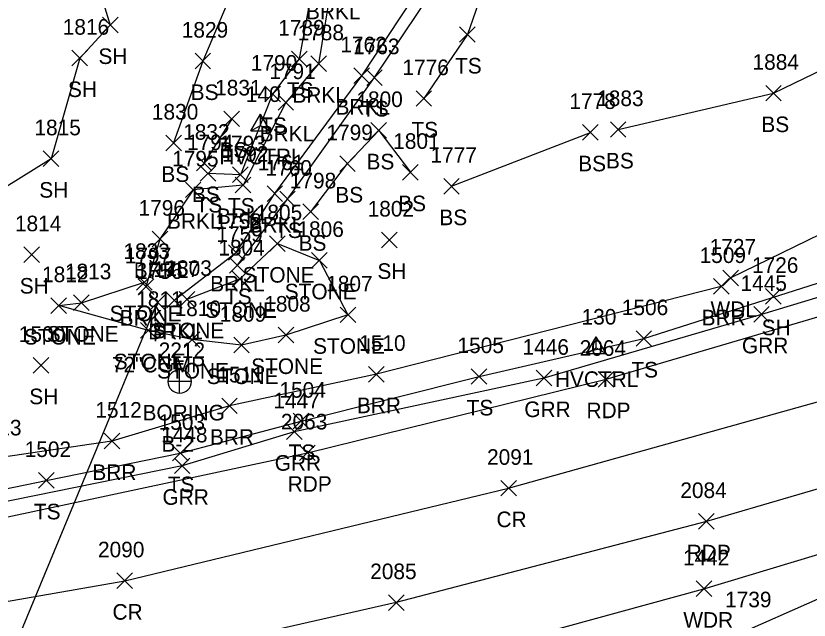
# Model space of a CAD drawing. Extents: x 1526508 to 1531550, y 369926 to 373082.
# Drawn here: x 1531067.4 to 1531169.1, y 370143.1 to 370220.6 of the extents above; entities that cross this region are included whole.
import ezdxf

# ---------------------------------------------------------------- set-up
doc = ezdxf.new("R2010")
doc.units = 0
for name, color, linetype in [('C_A', 7, 'Continuous'), ('C_I', 7, 'Continuous'), ('CPSM', 7, 'Continuous'), ('D_A', 7, 'Continuous'), ('D_C', 7, 'Continuous'), ('D_I', 7, 'Continuous'), ('D_TIC', 7, 'Continuous'), ('DCP', 7, 'Continuous'), ('G_A', 7, 'Continuous'), ('G_C', 7, 'Continuous'), ('G_I', 7, 'Continuous'), ('GA_P', 7, 'Continuous'), ('L_A', 7, 'Continuous'), ('L_I', 7, 'Continuous'), ('L_TIC', 7, 'Continuous'), ('LABL', 7, 'Continuous'), ('LASF', 7, 'Continuous'), ('LAWA', 7, 'Continuous'), ('LAWE', 7, 'Continuous'), ('LELB', 7, 'Continuous'), ('LSOGP', 7, 'Continuous'), ('P_A', 7, 'Continuous'), ('P_I', 7, 'Continuous'), ('P_TIC', 7, 'Continuous'), ('PET', 7, 'Continuous'), ('PRC', 7, 'Continuous'), ('R_A', 7, 'Continuous'), ('R_I', 7, 'Continuous'), ('R_TIC', 7, 'Continuous'), ('RGR', 7, 'Continuous')]:
    doc.layers.add(name, color=color, linetype=linetype)

msp = doc.modelspace()

# ---------------------------------------------------------------- linework, layer by layer
at = {"layer": 'CPSM'}
for p, q in [((1531097.55, 370205.87), (1531098.8, 370208.03)), ((1531100.05, 370205.87), (1531098.8, 370208.03)), ((1531098.8, 370206.59), (1531098.8, 370208.03)), ((1531097.55, 370205.87), (1531098.8, 370206.59)), ((1531097.55, 370205.87), (1531100.05, 370205.87)), ((1531098.8, 370206.59), (1531098.8, 370206.59)), ((1531098.8, 370206.59), (1531100.05, 370205.87)), ((1531140.6, 370177.3), (1531141.85, 370179.47)), ((1531143.1, 370177.3), (1531141.85, 370179.47)), ((1531141.85, 370178.03), (1531141.85, 370179.47)), ((1531140.6, 370177.3), (1531141.85, 370178.03)), ((1531140.6, 370177.3), (1531143.1, 370177.3)), ((1531141.85, 370178.03), (1531141.85, 370178.03)), ((1531141.85, 370178.03), (1531143.1, 370177.3))]:
    msp.add_line(p, q, dxfattribs=at)
at = {"layer": 'D_TIC'}
for points in [[(1531084.61, 370182.89), (1531086.61, 370184.89)], [(1531086.61, 370182.89), (1531084.61, 370184.89)]]:
    msp.add_lwpolyline(points, dxfattribs=at)
at = {"layer": 'DCP'}
msp.add_lwpolyline([(1531055.49, 370099.7), (1531060.38, 370123.1), (1531085.61, 370183.89)], dxfattribs=at)
at = {"layer": 'GA_P'}
for p, q in [((1531088.43, 370173.73), (1531088.43, 370175.23)), ((1531088.43, 370173.73), (1531086.93, 370173.73)), ((1531089.93, 370173.73), (1531088.43, 370173.73)), ((1531088.43, 370172.23), (1531088.43, 370173.73))]:
    msp.add_line(p, q, dxfattribs=at)
for start, end in [(90, 180), (0, 90), (180, 270), (270, 0)]:
    msp.add_arc((1531088.43, 370173.73), 1.5, start, end, dxfattribs=at)
at = {"layer": 'L_TIC'}
for points in [[(1531078.53, 370218.46), (1531080.53, 370220.46)], [(1531080.53, 370218.46), (1531078.53, 370220.46)], [(1531124.33, 370217.24), (1531126.33, 370219.24)], [(1531126.33, 370217.24), (1531124.33, 370219.24)], [(1531074.62, 370214.22), (1531076.62, 370216.22)], [(1531076.62, 370214.22), (1531074.62, 370216.22)], [(1531102.77, 370214.11), (1531104.77, 370216.11)], [(1531104.77, 370214.11), (1531102.77, 370216.11)], [(1531090.4, 370213.84), (1531092.4, 370215.84)], [(1531092.4, 370213.84), (1531090.4, 370215.84)], [(1531105.25, 370213.5), (1531107.25, 370215.5)], [(1531107.25, 370213.5), (1531105.25, 370215.5)], [(1531110.77, 370211.96), (1531112.77, 370213.96)], [(1531112.77, 370211.96), (1531110.77, 370213.96)], [(1531112.41, 370211.72), (1531114.41, 370213.72)], [(1531114.41, 370211.72), (1531112.41, 370213.72)], [(1531099.34, 370209.6), (1531101.34, 370211.6)], [(1531101.34, 370209.6), (1531099.34, 370211.6)], [(1531118.74, 370209.03), (1531120.74, 370211.03)], [(1531120.74, 370209.03), (1531118.74, 370211.03)], [(1531163.57, 370209.72), (1531165.57, 370211.72)], [(1531165.57, 370209.72), (1531163.57, 370211.72)], [(1531101.04, 370208.52), (1531103.04, 370210.52)], [(1531103.04, 370208.52), (1531101.04, 370210.52)], [(1531094.11, 370206.42), (1531096.11, 370208.42)], [(1531096.11, 370206.42), (1531094.11, 370208.42)], [(1531112.95, 370204.94), (1531114.95, 370206.94)], [(1531114.95, 370204.94), (1531112.95, 370206.94)], [(1531143.65, 370205.06), (1531145.65, 370207.06)], [(1531145.65, 370205.06), (1531143.65, 370207.06)], [(1531140.09, 370204.69), (1531142.09, 370206.69)], [(1531142.09, 370204.69), (1531140.09, 370206.69)], [(1531086.65, 370203.33), (1531088.65, 370205.33)], [(1531088.65, 370203.33), (1531086.65, 370205.33)], [(1531070.94, 370201.31), (1531072.94, 370203.31)], [(1531072.94, 370201.31), (1531070.94, 370203.31)], [(1531090.57, 370200.74), (1531092.57, 370202.74)], [(1531092.57, 370200.74), (1531090.57, 370202.74)], [(1531108.95, 370200.68), (1531110.95, 370202.68)], [(1531110.95, 370200.68), (1531108.95, 370202.68)], [(1531091.06, 370199.41), (1531093.06, 370201.41)], [(1531093.06, 370199.41), (1531091.06, 370201.41)], [(1531095.22, 370199.26), (1531097.22, 370201.26)], [(1531097.22, 370199.26), (1531095.22, 370201.26)], [(1531117.01, 370199.57), (1531119.01, 370201.57)], [(1531119.01, 370199.57), (1531117.01, 370201.57)], [(1531095.56, 370197.93), (1531097.56, 370199.93)], [(1531097.56, 370197.93), (1531095.56, 370199.93)], [(1531122.28, 370197.78), (1531124.28, 370199.78)], [(1531124.28, 370197.78), (1531122.28, 370199.78)], [(1531089.16, 370197.32), (1531091.16, 370199.32)], [(1531091.16, 370197.32), (1531089.16, 370199.32)], [(1531099.63, 370196.83), (1531101.63, 370198.83)], [(1531101.63, 370196.83), (1531099.63, 370198.83)], [(1531101.26, 370196.13), (1531103.26, 370198.13)], [(1531103.26, 370196.13), (1531101.26, 370198.13)], [(1531104.24, 370194.5), (1531106.24, 370196.5)], [(1531106.24, 370194.5), (1531104.24, 370196.5)], [(1531084.9, 370191), (1531086.9, 370193)], [(1531086.9, 370191), (1531084.9, 370193)], [(1531114.3, 370190.89), (1531116.3, 370192.89)], [(1531116.3, 370190.89), (1531114.3, 370192.89)], [(1531099.96, 370190.41), (1531101.96, 370192.41)], [(1531101.96, 370190.41), (1531099.96, 370192.41)], [(1531068.44, 370189), (1531070.44, 370191)], [(1531070.44, 370189), (1531068.44, 370191)], [(1531094.69, 370189.28), (1531096.69, 370191.28)], [(1531096.69, 370189.28), (1531094.69, 370191.28)], [(1531094.84, 370187.64), (1531096.84, 370189.64)], [(1531096.84, 370187.64), (1531094.84, 370189.64)], [(1531105.35, 370188.27), (1531107.35, 370190.27)], [(1531107.35, 370188.27), (1531105.35, 370190.27)], [(1531082.91, 370185.45), (1531084.91, 370187.45)], [(1531084.91, 370185.45), (1531082.91, 370187.45)], [(1531095.16, 370185.89), (1531097.16, 370187.89)], [(1531097.16, 370185.89), (1531095.16, 370187.89)], [(1531158.07, 370186.01), (1531160.07, 370188.01)], [(1531160.07, 370186.01), (1531158.07, 370188.01)], [(1531083.1, 370184.89), (1531085.1, 370186.89)], [(1531085.1, 370184.89), (1531083.1, 370186.89)], [(1531156.87, 370184.93), (1531158.87, 370186.93)], [(1531158.87, 370184.93), (1531156.87, 370186.93)], [(1531163.56, 370183.66), (1531165.56, 370185.66)], [(1531165.56, 370183.66), (1531163.56, 370185.66)], [(1531071.92, 370182.47), (1531073.92, 370184.47)], [(1531073.92, 370182.47), (1531071.92, 370184.47)], [(1531074.84, 370182.84), (1531076.84, 370184.84)], [(1531076.84, 370182.84), (1531074.84, 370184.84)], [(1531086.74, 370183.15), (1531088.74, 370185.15)], [(1531088.74, 370183.15), (1531086.74, 370185.15)], [(1531088.38, 370183.27), (1531090.38, 370185.27)], [(1531090.38, 370183.27), (1531088.38, 370185.27)], [(1531109, 370181.28), (1531111, 370183.28)], [(1531111, 370181.28), (1531109, 370183.28)], [(1531083.42, 370179.29), (1531085.42, 370181.29)], [(1531085.42, 370179.29), (1531083.42, 370181.29)], [(1531101.05, 370178.69), (1531103.05, 370180.69)], [(1531103.05, 370178.69), (1531101.05, 370180.69)], [(1531089, 370178.11), (1531091, 370180.11)], [(1531091, 370178.11), (1531089, 370180.11)], [(1531095.36, 370177.4), (1531097.36, 370179.4)], [(1531097.36, 370177.4), (1531095.36, 370179.4)], [(1531146.94, 370178.24), (1531148.94, 370180.24)], [(1531148.94, 370178.24), (1531146.94, 370180.24)], [(1531069.67, 370174.81), (1531071.67, 370176.81)], [(1531071.67, 370174.81), (1531069.67, 370176.81)], [(1531112.66, 370173.66), (1531114.66, 370175.66)], [(1531114.66, 370173.66), (1531112.66, 370175.66)], [(1531125.82, 370173.37), (1531127.82, 370175.37)], [(1531127.82, 370173.37), (1531125.82, 370175.37)], [(1531093.82, 370169.61), (1531095.82, 370171.61)], [(1531095.82, 370169.61), (1531093.82, 370171.61)], [(1531102.99, 370167.65), (1531104.99, 370169.65)], [(1531104.99, 370167.65), (1531102.99, 370169.65)], [(1531078.75, 370165.09), (1531080.75, 370167.09)], [(1531080.75, 370165.09), (1531078.75, 370167.09)], [(1531087.5, 370163.53), (1531089.5, 370165.53)], [(1531089.5, 370163.53), (1531087.5, 370165.53)], [(1531070.33, 370160.04), (1531072.33, 370162.04)], [(1531072.33, 370160.04), (1531070.33, 370162.04)], [(1531154.65, 370146.14), (1531156.65, 370148.14)], [(1531156.65, 370146.14), (1531154.65, 370148.14)]]:
    msp.add_lwpolyline(points, dxfattribs=at)
at = {"layer": 'LABL'}
msp.add_lwpolyline([(1531157.87, 370185.93), (1531113.66, 370174.66), (1531094.82, 370170.61), (1531079.75, 370166.09), (1531064.33, 370163.81), (1531055.99, 370163.16), (1531043.41, 370166.8)], dxfattribs=at)
at = {"layer": 'LASF'}
msp.add_lwpolyline([(1531089.38, 370184.27), (1531096.16, 370186.89), (1531100.96, 370191.41), (1531106.35, 370189.27), (1531110, 370182.28), (1531102.05, 370179.69), (1531096.36, 370178.4), (1531090, 370179.11), (1531084.42, 370180.29), (1531072.92, 370183.47), (1531075.84, 370183.84), (1531083.91, 370186.45)], dxfattribs=at)
at = {"layer": 'LAWA'}
for points in [[(1531159.07, 370187.01), (1531173.89, 370194.26), (1531191.12, 370197.26), (1531211.54, 370204.68), (1531235.67, 370211.51)], [(1531110.36, 370111.61), (1531088.81, 370117.3), (1531064.64, 370118.26), (1531064.75, 370123.38), (1531085.74, 370129.03), (1531112.09, 370135.21), (1531155.65, 370147.14), (1531210.22, 370163.6)]]:
    msp.add_lwpolyline(points, dxfattribs=at)
at = {"layer": 'LAWE'}
for points in [[(1531129.24, 370263.44), (1531122.24, 370251.12), (1531118.19, 370241.71), (1531111.75, 370236.24), (1531107.99, 370225.2), (1531106.25, 370214.5), (1531102.04, 370209.52), (1531096.56, 370198.93), (1531090.16, 370198.32), (1531085.9, 370192), (1531084.1, 370185.89)], [(1531087.74, 370184.15), (1531095.69, 370190.28), (1531100.63, 370197.83), (1531111.77, 370212.96), (1531123.37, 370230.51), (1531126.41, 370239.45), (1531131.95, 370252.37), (1531141.07, 370260.04)]]:
    msp.add_lwpolyline(points, dxfattribs=at)
at = {"layer": 'LELB'}
for points in [[(1531144.65, 370206.06), (1531164.57, 370210.72), (1531180.3, 370218.31), (1531196.61, 370223.05), (1531216.18, 370227.2), (1531246.26, 370234.32), (1531259.5, 370237.9), (1531291.92, 370247.44), (1531321.67, 370253.97), (1531341.88, 370260.29), (1531377.42, 370272.37), (1531403.24, 370281.83), (1531425.1, 370287.02), (1531443.59, 370293.1), (1531470.33, 370300.31), (1531494.61, 370309.28), (1531517.9, 370316.82)], [(1531123.52, 370266.99), (1531115.32, 370250.55), (1531099.57, 370234.22), (1531091.4, 370214.84), (1531087.65, 370204.33)], [(1531095.84, 370188.64), (1531102.26, 370197.13), (1531113.41, 370212.72), (1531124.43, 370229.18), (1531128.27, 370238.2), (1531133.55, 370250.63), (1531142.18, 370258.83)], [(1531148.94, 370252.7), (1531135.43, 370239.75), (1531128.72, 370228), (1531125.33, 370218.24), (1531119.74, 370210.03)], [(1531108.94, 370236.69), (1531105.71, 370225.84), (1531103.77, 370215.11), (1531100.34, 370210.6), (1531096.22, 370200.26), (1531092.06, 370200.41)], [(1531095.11, 370207.42), (1531091.57, 370201.74)], [(1531105.24, 370195.5), (1531109.95, 370201.68), (1531113.95, 370205.94), (1531118.01, 370200.57)], [(1531123.28, 370198.78), (1531141.09, 370205.69)], [(1531052, 370157.05), (1531071.33, 370161.04), (1531088.5, 370164.53), (1531103.99, 370168.65), (1531126.82, 370174.37), (1531147.94, 370179.24), (1531175.97, 370188.19), (1531192.8, 370192.85)], [(1531210.97, 370157.64), (1531190.22, 370151.95), (1531176.55, 370148.6), (1531161.06, 370141.76), (1531149.58, 370137.75), (1531135.28, 370131.25)]]:
    msp.add_lwpolyline(points, dxfattribs=at)
at = {"layer": 'LSOGP'}
msp.add_lwpolyline([(1531177.54, 370326.67), (1531158.16, 370311.5), (1531136.38, 370307.37), (1531128.26, 370297.45), (1531117.26, 370278.94), (1531108.22, 370270.78), (1531090.84, 370249.56), (1531076.08, 370230.71), (1531079.53, 370219.46), (1531075.62, 370215.22), (1531071.94, 370202.31), (1531045.19, 370185.67), (1531041.08, 370185.67), (1531037.14, 370186.29), (1531030.53, 370189.52), (1531026.78, 370191.04), (1531014.55, 370193.66), (1531012.24, 370193.81), (1531009.22, 370193.47), (1530986.53, 370183.09), (1530962.18, 370174.64)], dxfattribs=at)
at = {"layer": 'P_TIC'}
for points in [[(1531142.1, 370173.02), (1531144.1, 370175.02)], [(1531144.1, 370173.02), (1531142.1, 370175.02)], [(1531103.8, 370163.58), (1531105.8, 370165.58)], [(1531105.8, 370163.58), (1531103.8, 370165.58)], [(1531129.61, 370159.04), (1531131.61, 370161.04)], [(1531131.61, 370159.04), (1531129.61, 370161.04)], [(1531154.96, 370154.78), (1531156.96, 370156.78)], [(1531156.96, 370154.78), (1531154.96, 370156.78)], [(1531080.39, 370147.17), (1531082.39, 370149.17)], [(1531082.39, 370147.17), (1531080.39, 370149.17)], [(1531115.2, 370144.37), (1531117.2, 370146.37)], [(1531117.2, 370144.37), (1531115.2, 370146.37)]]:
    msp.add_lwpolyline(points, dxfattribs=at)
at = {"layer": 'PET'}
for points in [[(1531036.19, 370150.91), (1531061.97, 370155.43), (1531104.8, 370164.58), (1531143.1, 370174.02), (1531180.11, 370184.91), (1531218.48, 370196.81), (1531260.06, 370210.9), (1531302.03, 370225.36), (1531352.57, 370243.2), (1531401.62, 370260.1), (1531448.12, 370277.05), (1531486.93, 370290.59), (1531531.91, 370306.21)], [(1531538.54, 370286.02), (1531506.28, 370274.48), (1531462.76, 370259.55), (1531429.61, 370248.08), (1531393.11, 370234.63), (1531350.62, 370219.92), (1531310.67, 370205.95), (1531271.31, 370192.3), (1531228.45, 370178.01), (1531188.4, 370165.28), (1531155.96, 370155.78), (1531116.2, 370145.37), (1531081.97, 370137.61), (1531057.06, 370132.93), (1531039.15, 370130.45)]]:
    msp.add_lwpolyline(points, dxfattribs=at)
at = {"layer": 'PRC'}
msp.add_lwpolyline([(1531037.76, 370140.53), (1531081.39, 370148.17), (1531130.61, 370160.04), (1531176.3, 370172.81), (1531216.72, 370185.49), (1531265.37, 370201.61), (1531315.14, 370219.14), (1531364.47, 370236.54), (1531403.01, 370250.24), (1531441.26, 370263.86), (1531484.78, 370279.08), (1531519.83, 370291.48), (1531535.78, 370296.89)], dxfattribs=at)
at = {"layer": 'R_TIC'}
for points in [[(1531162.03, 370181.34), (1531164.03, 370183.34)], [(1531164.03, 370181.34), (1531162.03, 370183.34)], [(1531134.13, 370173.16), (1531136.13, 370175.16)], [(1531136.13, 370173.16), (1531134.13, 370175.16)], [(1531102.13, 370166.28), (1531104.13, 370168.28)], [(1531104.13, 370166.28), (1531102.13, 370168.28)], [(1531087.75, 370161.91), (1531089.75, 370163.91)], [(1531089.75, 370161.91), (1531087.75, 370163.91)]]:
    msp.add_lwpolyline(points, dxfattribs=at)
at = {"layer": 'RGR'}
msp.add_lwpolyline([(1531193.3, 370191.46), (1531163.03, 370182.34), (1531135.13, 370174.16), (1531103.13, 370167.28), (1531088.75, 370162.91), (1531056.08, 370156.26)], dxfattribs=at)

# ---------------------------------------------------------------- texts
at = {"layer": 'C_A'}
for p in [(1531093.5, 370201.59), (1531136.54, 370173.03)]:
    msp.add_text('HVCTRL', height=2, dxfattribs=at).set_placement(p)
at = {"layer": 'C_I'}
for s, p in [('140', (1531096.92, 370209.59)), ('130', (1531139.96, 370181.03))]:
    msp.add_text(s, height=2, dxfattribs=at).set_placement(p)
at = {"layer": 'D_A'}
msp.add_text('P', height=2, dxfattribs=at).set_placement((1531084.99, 370178.89))
at = {"layer": 'D_C'}
msp.add_text('72"CGMP', height=2, dxfattribs=at).set_placement((1531079.74, 370174.89))
at = {"layer": 'D_I'}
msp.add_text('1756', height=2, dxfattribs=at).set_placement((1531082.86, 370186.89))
at = {"layer": 'G_A'}
msp.add_text('BORING', height=2, dxfattribs=at).set_placement((1531083.67, 370168.73))
at = {"layer": 'G_C'}
msp.add_text('B-2', height=2, dxfattribs=at).set_placement((1531086.1, 370164.73))
at = {"layer": 'G_I'}
msp.add_text('2212', height=2, dxfattribs=at).set_placement((1531085.74, 370176.73))
at = {"layer": 'L_A'}
for s, p in [('BRKL', (1531104.63, 370220.2)), ('SH', (1531078.02, 370214.46)), ('TS', (1531123.74, 370213.24)), ('SH', (1531074.11, 370210.22)), ('BS', (1531089.84, 370209.84)), ('TS', (1531102.18, 370210.11)), ('BRKL', (1531102.89, 370209.5)), ('BRKL', (1531108.41, 370207.96)), ('TS', (1531111.82, 370207.72)), ('BS', (1531163.01, 370205.72)), ('TS', (1531098.75, 370205.6)), ('TS', (1531118.15, 370205.03)), ('BRKL', (1531098.69, 370204.52)), ('BS', (1531093.55, 370202.42)), ('BS', (1531112.39, 370200.94)), ('BS', (1531139.53, 370200.69)), ('BS', (1531143.09, 370201.06)), ('BS', (1531086.09, 370199.33)), ('SH', (1531070.43, 370197.31)), ('BS', (1531090.01, 370196.74)), ('BS', (1531108.39, 370196.68)), ('BS', (1531116.45, 370195.57)), ('TS', (1531090.47, 370195.41)), ('TS', (1531094.63, 370195.26)), ('BRKL', (1531093.21, 370193.93)), ('BS', (1531121.73, 370193.78)), ('BRKL', (1531086.81, 370193.32)), ('BRKL', (1531097.28, 370192.83)), ('TS', (1531100.67, 370192.13)), ('BS', (1531103.68, 370190.5)), ('BRKL', (1531082.55, 370187)), ('STONE', (1531096.51, 370186.41)), ('SH', (1531113.79, 370186.89)), ('SH', (1531067.93, 370185)), ('BRKL', (1531092.34, 370185.28)), ('TS', (1531094.25, 370183.64)), ('STONE', (1531101.9, 370184.27)), ('STONE', (1531079.46, 370181.45)), ('STONE', (1531091.7, 370181.89)), ('WDL', (1531156.49, 370182.01)), ('BRKL', (1531080.74, 370180.89)), ('BRR', (1531155.35, 370180.93)), ('STONE', (1531084.93, 370179.27)), ('SH', (1531163.05, 370179.66)), ('STONE', (1531068.46, 370178.47)), ('STONE', (1531071.39, 370178.84)), ('BRKL', (1531084.39, 370179.15)), ('STONE', (1531105.54, 370177.28)), ('STONE', (1531079.97, 370175.29)), ('STONE', (1531097.6, 370174.69)), ('TS', (1531146.35, 370174.24)), ('STONE', (1531085.54, 370174.11)), ('STONE', (1531091.9, 370173.4)), ('SH', (1531069.15, 370170.81)), ('BRR', (1531111.15, 370169.66)), ('TS', (1531125.23, 370169.37)), ('BRR', (1531092.31, 370165.61)), ('TS', (1531102.4, 370163.65)), ('BRR', (1531077.24, 370161.09)), ('TS', (1531086.91, 370159.53)), ('TS', (1531069.74, 370156.04)), ('WDR', (1531153.01, 370142.14))]:
    msp.add_text(s, height=2, dxfattribs=at).set_placement(p)
at = {"layer": 'L_I'}
for s, p in [('1816', (1531073.44, 370218.22)), ('1789', (1531101.07, 370218.11)), ('1829', (1531088.7, 370217.84)), ('1788', (1531103.55, 370217.5)), ('1762', (1531109.03, 370215.96)), ('1763', (1531110.67, 370215.72)), ('1790', (1531097.56, 370213.6)), ('1776', (1531116.99, 370213.03)), ('1884', (1531161.88, 370213.72)), ('1791', (1531099.92, 370212.52)), ('1831', (1531092.98, 370210.42)), ('1800', (1531111.09, 370208.94)), ('1883', (1531141.96, 370209.06)), ('1778', (1531138.4, 370208.69)), ('1830', (1531084.87, 370207.33)), ('1815', (1531069.81, 370205.31)), ('1832', (1531088.88, 370204.74)), ('1799', (1531107.25, 370204.68)), ('1794', (1531089.37, 370203.41)), ('1793', (1531093.53, 370203.26)), ('1801', (1531115.81, 370203.57)), ('1792', (1531093.87, 370201.93)), ('1777', (1531120.59, 370201.78)), ('1795', (1531087.47, 370201.32)), ('1761', (1531098.46, 370200.83)), ('1760', (1531099.44, 370200.13)), ('1798', (1531102.55, 370198.5)), ('1796', (1531083.16, 370195)), ('1802', (1531112.53, 370194.89)), ('1805', (1531098.19, 370194.41)), ('1814', (1531067.31, 370193)), ('1758', (1531093, 370193.28)), ('1759', (1531093.14, 370191.64)), ('1806', (1531103.53, 370192.27)), ('1833', (1531081.22, 370189.45)), ('1804', (1531093.39, 370189.89)), ('1727', (1531156.38, 370190.01)), ('1797', (1531081.4, 370188.89)), ('1509', (1531155.09, 370188.93)), ('1726', (1531161.81, 370187.66)), ('1812', (1531070.79, 370186.47)), ('1813', (1531073.72, 370186.84)), ('1757', (1531085.05, 370187.15)), ('1803', (1531086.61, 370187.27)), ('1807', (1531107.22, 370185.28)), ('1811', (1531082.86, 370183.29)), ('1808', (1531099.28, 370182.69)), ('1810', (1531087.78, 370182.11)), ('1809', (1531093.58, 370181.4)), ('1506', (1531145.12, 370182.24)), ('1500', (1531067.81, 370178.81)), ('1510', (1531111.45, 370177.66)), ('1505', (1531124.05, 370177.37)), ('1511', (1531093.26, 370173.61)), ('1504', (1531101.22, 370171.65)), ('1512', (1531077.62, 370169.09)), ('1503', (1531085.73, 370167.53)), ('1513', (1531062.21, 370166.81)), ('1502', (1531068.56, 370164.04)), ('1442', (1531152.96, 370150.14)), ('1739', (1531158.36, 370144.76))]:
    msp.add_text(s, height=2, dxfattribs=at).set_placement(p)
at = {"layer": 'P_A'}
for s, p in [('RDP', (1531140.59, 370169.02)), ('RDP', (1531102.28, 370159.58)), ('CR', (1531129.05, 370155.04)), ('RDP', (1531153.44, 370150.78)), ('CR', (1531079.82, 370143.17))]:
    msp.add_text(s, height=2, dxfattribs=at).set_placement(p)
at = {"layer": 'P_I'}
for s, p in [('2064', (1531139.71, 370177.02)), ('2063', (1531101.41, 370167.58)), ('2091', (1531127.84, 370163.04)), ('2084', (1531152.62, 370158.78)), ('2090', (1531077.96, 370151.17)), ('2085', (1531112.86, 370148.37))]:
    msp.add_text(s, height=2, dxfattribs=at).set_placement(p)
at = {"layer": 'R_A'}
for p in [(1531160.52, 370177.34), (1531132.62, 370169.16), (1531100.62, 370162.28), (1531086.23, 370157.91)]:
    msp.add_text('GRR', height=2, dxfattribs=at).set_placement(p)
at = {"layer": 'R_I'}
for s, p in [('1445', (1531160.34, 370185.34)), ('1446', (1531132.39, 370177.16)), ('1447', (1531100.44, 370170.28)), ('1448', (1531086.05, 370165.91))]:
    msp.add_text(s, height=2, dxfattribs=at).set_placement(p)

doc.saveas('drawing.dxf')
